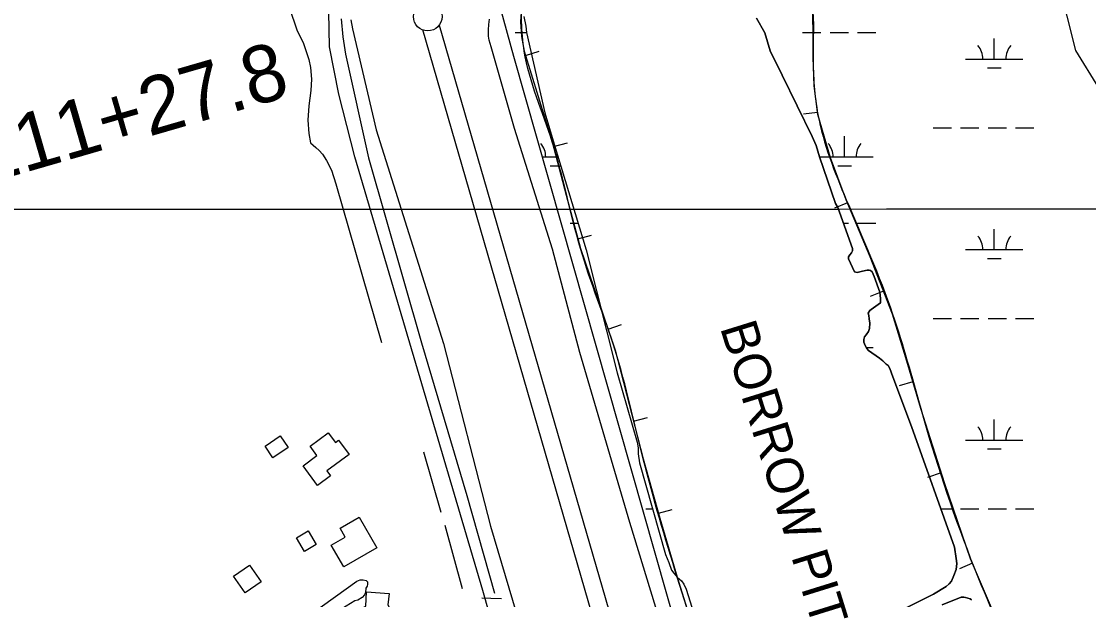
# Model space of a CAD drawing. Extents: x 3281947 to 3319794, y 715894 to 741249.
# Drawn here: x 3291541 to 3293405, y 732714 to 733724 of the extents above; entities that cross this region are included whole.
import ezdxf

# ---------------------------------------------------------------- set-up
doc = ezdxf.new("R2010")
doc.units = 0
for name, color, linetype in [('V-BLDG-OTLN', 7, 'Continuous'), ('V-BORW-IDEN', 7, 'Continuous'), ('V-BORW-LINE', 7, 'Continuous'), ('V-DTCH-CNTR', 7, 'Continuous'), ('V-GRID-MAJR', 7, 'Continuous'), ('V-LEVE-TOET', 7, 'Continuous'), ('V-ROAD-CNTR', 7, 'Continuous'), ('V-SITE-VEGE', 7, 'Continuous'), ('V-SURV-IDEN', 7, 'Continuous'), ('V-SURV-LINE', 7, 'Continuous'), ('V-TOPO-SHOR', 7, 'Continuous'), ('V-WETL-SWMP', 7, 'Continuous')]:
    doc.layers.add(name, color=color, linetype=linetype)

msp = doc.modelspace()

# ---------------------------------------------------------------- linework, layer by layer
at = {"layer": 'V-BLDG-OTLN'}
for points in [[(3291980.4, 732961.6), (3291966.5, 732981.9), (3291993.1, 733000.2), (3292007.1, 732979.9)], [(3292074.6, 732938.7), (3292080.9, 732930.3), (3292058.4, 732913.6), (3292033, 732947.7), (3292057.2, 732965.7), (3292045.2, 732981.9), (3292077, 733005.6), (3292089.7, 732988.6), (3292094.9, 732992.5), (3292113.4, 732967.6)], [(3292130.9, 732858), (3292161.8, 732804.7), (3292103.9, 732771.1), (3292081.9, 732808.9), (3292106.5, 732823.2), (3292097.6, 732838.7)], [(3292035.2, 732798.1), (3292021.3, 732821.8), (3292042.1, 732834), (3292056, 732810.3)], [(3291931.6, 732725.8), (3291911.5, 732755.2), (3291939.6, 732774.5), (3291959.8, 732745)], [(3292142.5, 732702.7), (3292143.7, 732727.6), (3292183.2, 732724.9), (3292181.2, 732705.2), (3292200.2, 732667.4), (3292166.1, 732651.6), (3292157.7, 732668.7), (3292127.1, 732655.4), (3292110.3, 732687.3)]]:
    msp.add_lwpolyline(points, close=True, dxfattribs=at)
at = {"layer": 'V-BORW-LINE'}
for p, q in [((3292421.4, 733664.4), (3292445.4, 733671.7)), ((3292931.5, 733564.9), (3292906.7, 733561.8)), ((3292470.3, 733505.2), (3292494.6, 733511.4)), ((3292983.8, 733407), (3292960.7, 733397.4)), ((3292512.8, 733344.1), (3292536.9, 733350.5)), ((3293046.7, 733252.7), (3293023.4, 733243.6)), ((3292565.6, 733186.1), (3292589.3, 733194.2)), ((3293097.8, 733094.3), (3293073.8, 733087.3)), ((3292610, 733025.6), (3292634.2, 733031.9)), ((3293147.4, 732935.3), (3293123.6, 732927.6)), ((3292653.6, 732864.8), (3292677.6, 732871.6)), ((3293202, 732777.9), (3293179, 732768.1))]:
    msp.add_line(p, q, dxfattribs=at)
for points in [[(3292416, 733774.3), (3292412.7, 733722.9), (3292414.5, 733697.2), (3292419.2, 733671.8), (3292443.4, 733592.3), (3292468.2, 733513.4), (3292492.4, 733420.2), (3292517.3, 733327.2), (3292547.9, 733238.5), (3292578, 733149.6), (3292602.5, 733054.8), (3292626.9, 732959.9), (3292655.9, 732856.5), (3292686.3, 732753.5), (3292718.4, 732650.6)], [(3293236.9, 732695.8), (3293198.7, 732785.6), (3293153.6, 732916.1), (3293111.5, 733047.6), (3293087.3, 733130.2), (3293062.5, 733212.5), (3293023.2, 733312.7), (3292981.6, 733412.2), (3292953.9, 733485.6), (3292932, 733561), (3292925.7, 733610.9), (3292923.7, 733661.1), (3292923.9, 733706.9), (3292922.7, 733752.5)]]:
    msp.add_lwpolyline(points, dxfattribs=at)
msp.add_spline([(3293535.9, 730584.4), (3293535.4, 730585.3), (3293497, 730657.8), (3293473.2, 730709), (3293458.5, 730751), (3293474.3, 730774.9), (3293498.1, 730803.8), (3293503.4, 730822.7), (3293477.8, 730865.6), (3293442, 730902.7), (3293433.9, 730945), (3293411.4, 730975.9), (3293373.6, 730999.6), (3293329.4, 731009.5), (3293303.1, 731048.1), (3293262.2, 731107.9), (3293205.3, 731214.8), (3293152.6, 731305), (3293107.1, 731394.1), (3293067.5, 731500.7), (3293026.1, 731639), (3292993.6, 731735.4), (3292952.7, 731872.8), (3292925.4, 731981.1), (3292877.6, 732144.9), (3292823.1, 732324.3), (3292751.1, 732547.8), (3292686.3, 732753.5), (3292626.9, 732959.9), (3292578, 733149.6), (3292517.3, 733327.2), (3292468.2, 733513.4), (3292419.2, 733671.8), (3292416, 733774.3), (3292443.1, 733955.9), (3292470.5, 734116.1), (3292505.3, 734342.4), (3292539, 734502.7), (3292585.4, 734750.4), (3292605.6, 734909.3), (3292653.5, 735109.1), (3292667, 735197.9), (3292695.9, 735272.4), (3292816.4, 735423.9), (3292992.8, 735589.4), (3293118.5, 735717.8), (3293151.4, 735720.6), (3293212.8, 735688.5), (3293267.6, 735628.9), (3293299.6, 735578.7), (3293301.8, 735551.8), (3293258, 735404.8), (3293178.9, 735247.8), (3293118.6, 735154.6), (3293020.3, 735075.8), (3292963, 735023.3), (3292899.5, 734947.4), (3292877.5, 734825.5), (3292893.6, 734715.3), (3292909.1, 734596.9), (3292894.2, 734486.7), (3292877, 734359.2), (3292869.2, 734210.8), (3292882, 734024.1), (3292899.4, 733885.4), (3292922.7, 733752.5), (3292923.7, 733661.1), (3292932, 733561), (3292981.6, 733412.2), (3293062.5, 733212.5), (3293111.5, 733047.6), (3293198.7, 732785.6), (3293276, 732606.5), (3293315.6, 732497), (3293336.7, 732448.1), (3293389.1, 732447.8), (3293396.1, 732434.3), (3293380.9, 732420.2), (3293299, 732384.1), (3293266.7, 732364.9), (3293242, 732348.4), (3293249.1, 732332.4), (3293352.9, 732375.1), (3293457.9, 732401.3), (3293485.1, 732328.5), (3293556.5, 732096.9), (3293588.1, 731935.2), (3293608.4, 731793.7), (3293628.6, 731696.8), (3293641.6, 731601.6), (3293698.6, 731490.3), (3293768.8, 731439), (3293849.4, 731356), (3293937.4, 731250.3), (3293976, 731184.6), (3294065.4, 731012.3)], degree=3, dxfattribs=at)
at = {"layer": 'V-DTCH-CNTR'}
msp.add_lwpolyline([(3292009.4, 733746.9), (3292022.3, 733708.8), (3292033.9, 733685), (3292042.9, 733657.3), (3292045.8, 733643), (3292047.8, 733623), (3292046.3, 733603.2), (3292043.3, 733576.1), (3292041.5, 733551.3), (3292043.2, 733527.7), (3292046.1, 733511.8), (3292055.4, 733503.3), (3292061.2, 733498.5), (3292066.6, 733491.9), (3292074, 733481.1), (3292082.6, 733464.2), (3292090.1, 733440.1), (3292169.7, 733163.1)], dxfattribs=at)
at = {"layer": 'V-GRID-MAJR'}
msp.add_spline([(3286081.5, 733394.4), (3291329.7, 733395.6), (3296577.9, 733397.5), (3301826.1, 733400.1), (3307074.3, 733403.6), (3312322.5, 733407.8), (3317570.7, 733412.7)], degree=3, dxfattribs=at)
at = {"layer": 'V-LEVE-TOET'}
for points in [[(3292116.6, 733726.4), (3292119.1, 733710.8), (3292160.5, 733534.6), (3292278.1, 733161.5), (3292360.2, 732842.1), (3292398.4, 732713.4), (3292457.8, 732512.4), (3292537.4, 732193.7), (3292611.6, 731908.2), (3292708.8, 731568.3), (3292740.3, 731460.7), (3292780.4, 731364), (3292812.9, 731289.4), (3292841.9, 731225.5), (3292874.9, 731155.3), (3293007.9, 730907.9)], [(3292728.7, 732439.8), (3292603.7, 732848.8), (3292516.4, 733145.5), (3292468.8, 733326.1), (3292402.3, 733536.6), (3292361.3, 733679.4), (3292358, 733691), (3292357, 733697.8), (3292356.8, 733702.6), (3292356.7, 733709.2), (3292357.2, 733718), (3292358.6, 733727.4)]]:
    msp.add_lwpolyline(points, dxfattribs=at)
at = {"layer": 'V-ROAD-CNTR'}
for points in [[(3292971.1, 730923), (3292872, 731117), (3292817.2, 731219.5), (3292783.6, 731284), (3292753.8, 731349.2), (3292730.2, 731404.5), (3292711.3, 731460.3), (3292655.9, 731658.9), (3292493.2, 732214.9), (3292347.1, 732730.2), (3292123.3, 733487.2), (3292095.5, 733596.9), (3292079.2, 733679.3), (3292077.9, 733740.5)], [(3292379.2, 732715.4), (3292360.7, 732715.9), (3292345, 732716.4)]]:
    msp.add_lwpolyline(points, dxfattribs=at)
at = {"layer": 'V-SITE-VEGE'}
for points in [[(3292824.7, 733729.2), (3292839.3, 733704), (3292848.4, 733672.5), (3292869.6, 733630), (3292922, 733522.9), (3292929.1, 733507.1), (3292935, 733487.2), (3292962.5, 733405.8), (3292967, 733398.8), (3292992.6, 733327.1), (3292992.6, 733323.1), (3292990.7, 733319.4), (3292987.5, 733316.1), (3292985.2, 733312.6), (3292985.4, 733309.1), (3292995.8, 733286.7), (3293000.5, 733285.5), (3293005.4, 733286.3), (3293010.1, 733287.5), (3293018.2, 733289.1), (3293021.7, 733289.6), (3293024.1, 733288.7), (3293026.7, 733286.4), (3293030.2, 733278.2), (3293039.9, 733250.9), (3293041.4, 733240.1), (3293041.4, 733232.2), (3293028.8, 733223.7), (3293024.9, 733220.9), (3293022.5, 733219), (3293020, 733214.3), (3293020.9, 733209.9), (3293021.4, 733204.5), (3293022.9, 733196.6), (3293022.2, 733187.7), (3293020.1, 733182.5), (3293016.2, 733176.2), (3293013.6, 733172.9), (3293012.2, 733168), (3293012.3, 733163.8), (3293014.6, 733157.7), (3293017.5, 733152.6), (3293020.3, 733149.3), (3293039.8, 733135.4), (3293045.4, 733131), (3293051.3, 733125.4), (3293054.8, 733122.6), (3293057.6, 733117.7), (3293062.6, 733103.2), (3293095.2, 733016.2), (3293170.6, 732805.9), (3293173.5, 732786), (3293174.7, 732776.9), (3293173.5, 732766.9), (3293169.6, 732756.3), (3293165.2, 732746.5), (3293161.3, 732741.5), (3293155.9, 732737.3), (3293133.8, 732723.7), (3293058, 732685.9)], [(3293148.8, 732704.8), (3293182.2, 732718.5), (3293186.9, 732718.3), (3293189.9, 732717.8), (3293193.9, 732716.5), (3293197.6, 732715.5), (3293200.4, 732713.9)]]:
    msp.add_lwpolyline(points, dxfattribs=at)
msp.add_lwpolyline([(3292032.1, 732673.3), (3292048.2, 732689.7), (3292127.1, 732746.5), (3292132.5, 732748.5), (3292137.9, 732748.4), (3292143, 732747.7), (3292145.3, 732744.9), (3292145.6, 732741.2), (3292144.6, 732737.6), (3292142.5, 732733.9), (3292141.8, 732726.8), (3292140.4, 732722.7), (3292136.2, 732718), (3292128.4, 732713.4), (3292123.4, 732712.2), (3292070.1, 732679.3), (3292049.3, 732659.7), (3292045.7, 732654.9), (3292040, 732652.2), (3292034.3, 732653.4), (3292031.6, 732656.7), (3292030.4, 732661.1), (3292030.7, 732665.1)], close=True, dxfattribs=at)
at = {"layer": 'V-SURV-LINE'}
for points in [[(3292688.7, 732167.4), (3292241.9, 733708.8)], [(3292270.7, 733717.1), (3292717.5, 732175.8)]]:
    msp.add_lwpolyline(points, dxfattribs=at)
msp.add_circle((3292250.7, 733732.1), 25, dxfattribs=at)
at = {"layer": 'V-TOPO-SHOR'}
for p, q in [((3292274, 732866), (3292244, 732971.5)), ((3292311.3, 732732.7), (3292281.3, 732843.5))]:
    msp.add_line(p, q, dxfattribs=at)
msp.add_lwpolyline([(3292099.2, 733728.4), (3292102.3, 733696.8), (3292106.8, 733666.2), (3292147.3, 733485.4), (3292239.5, 733162.4), (3292319, 732896), (3292367, 732725.1)], dxfattribs=at)
at = {"layer": 'V-WETL-SWMP'}
for p, q in [((3292403.3, 733704.3), (3292423.4, 733704.3)), ((3292905.2, 733704.3), (3292937.2, 733704.3)), ((3292953.2, 733704.3), (3292985.2, 733704.3)), ((3293001.2, 733704.3), (3293033.2, 733704.3)), ((3293240, 733657.9), (3293240, 733693.9)), ((3293190, 733657.9), (3293290, 733657.9)), ((3293228, 733642.4), (3293252, 733642.4)), ((3293133.2, 733537.8), (3293165.2, 733537.8)), ((3293181.2, 733537.8), (3293213.2, 733537.8)), ((3293229.2, 733537.8), (3293261.2, 733537.8)), ((3293277.2, 733537.8), (3293309.2, 733537.8)), ((3292978.6, 733487.1), (3292978.6, 733523.1)), ((3292450.4, 733487.1), (3292478.3, 733487.1)), ((3292476.7, 733487.1), (3292476.7, 733492.5)), ((3292935.1, 733487.1), (3293028.6, 733487.1)), ((3292464.7, 733471.6), (3292483, 733471.6)), ((3292966.6, 733471.6), (3292990.6, 733471.6)), ((3292483.2, 733371.6), (3292483.3, 733371.6)), ((3292499.3, 733371.6), (3292513.4, 733371.6)), ((3292976.7, 733371.6), (3292985.2, 733371.6)), ((3293001.2, 733371.6), (3293033.2, 733371.6)), ((3293240, 733325.2), (3293240, 733361.2)), ((3293190, 733325.2), (3293290, 733325.2)), ((3293228, 733309.8), (3293252, 733309.8)), ((3293133.2, 733205.1), (3293165.2, 733205.1)), ((3293181.2, 733205.1), (3293213.2, 733205.1)), ((3293229.2, 733205.1), (3293261.2, 733205.1)), ((3293277.2, 733205.1), (3293309.2, 733205.1)), ((3293016.5, 733154.4), (3293028.6, 733154.4)), ((3293240, 732992.5), (3293240, 733028.5)), ((3293190, 732992.5), (3293290, 732992.5)), ((3293228, 732977.1), (3293252, 732977.1)), ((3292631.3, 732872.5), (3292643.3, 732872.5)), ((3293146.7, 732872.5), (3293165.2, 732872.5)), ((3293181.2, 732872.5), (3293213.2, 732872.5)), ((3293229.2, 732872.5), (3293261.2, 732872.5)), ((3293277.2, 732872.5), (3293309.2, 732872.5))]:
    msp.add_line(p, q, dxfattribs=at)
for points in [[(3293242.1, 736812), (3293232.1, 735969.6), (3293242.1, 735829.2), (3293272.1, 735779.1), (3293346.9, 735732.1), (3293357.8, 735673.5), (3293299.3, 735657.1), (3293212, 735769), (3293184.2, 735772.3), (3293151.3, 735776), (3293101.8, 735759), (3293021.6, 735688.8), (3292891.3, 735548.4), (3292761.1, 735398), (3292660.9, 735297.7), (3292620.8, 735237.5), (3292370.3, 733773.3), (3292400.3, 733663), (3292811.2, 732218.9), (3292828.6, 732036.6), (3293081.7, 731326.4), (3293270.4, 730981.3)], [(3294819.9, 730595.5), (3294614.9, 731005.5), (3294474.6, 731296.3), (3294354.4, 731617.2), (3294214.1, 731787.7), (3294073.8, 731978.2), (3293562.7, 733201.7), (3293462.5, 733542.7), (3293382.4, 733673.1), (3293352.3, 733793.4), (3293412.4, 733883.7), (3293492.6, 733913.7), (3293612.8, 733883.7), (3293673, 733813.5), (3293763.1, 733713.2)], [(3292418.6, 733732.2), (3292421.7, 733715.4), (3292423.4, 733704.2), (3292455.2, 733564.3), (3292471.6, 733509.4), (3292527.6, 733325), (3292581.4, 733109.9), (3292616.3, 732989.2), (3292618.2, 732978.9), (3292618.3, 732968.4), (3292620.7, 732953), (3292665.6, 732793), (3292671.8, 732779), (3292676.5, 732765.5), (3292680.5, 732760.1), (3292686.2, 732753.6), (3292690.4, 732750.1), (3292693.7, 732746.9), (3292698.1, 732741.3), (3292701.9, 732732.2), (3292732.3, 732636.5)], [(3293051.3, 733125.4), (3293045.4, 733131), (3293039.8, 733135.4), (3293020.3, 733149.3), (3293017.5, 733152.6), (3293014.6, 733157.7), (3293012.3, 733163.8), (3293012.2, 733168), (3293013.6, 733172.9), (3293016.2, 733176.2), (3293020.1, 733182.5), (3293022.2, 733187.7), (3293022.9, 733196.6), (3293021.4, 733204.5), (3293020.9, 733209.9), (3293020, 733214.3), (3293022.5, 733219), (3293024.9, 733220.9), (3293028.8, 733223.7), (3293041.4, 733232.2), (3293041.4, 733240.1), (3293039.9, 733250.9), (3293030.2, 733278.2), (3293026.7, 733286.4), (3293024.1, 733288.7), (3293021.7, 733289.6), (3293018.2, 733289.1), (3293010.1, 733287.4), (3293005.4, 733286.3), (3293000.5, 733285.5), (3292995.8, 733286.7), (3292985.4, 733309.1), (3292985.2, 733312.6), (3292987.5, 733316.1), (3292990.7, 733319.4), (3292992.6, 733323.1), (3292992.6, 733327.1), (3292967, 733398.8), (3292962.5, 733405.8), (3292935, 733487.2), (3292929.1, 733507.1), (3292922, 733522.9), (3292869.6, 733630), (3292848.4, 733672.5), (3292839.3, 733704), (3292824.7, 733729.2)], [(3293058, 732685.9), (3293133.8, 732723.7), (3293155.9, 732737.3), (3293161.3, 732741.5), (3293165.2, 732746.5), (3293169.6, 732756.3), (3293173.5, 732766.9), (3293174.7, 732776.9), (3293173.5, 732786), (3293170.6, 732805.9), (3293095.2, 733016.2), (3293062.6, 733103.2), (3293057.6, 733117.7), (3293054.8, 733122.6), (3293051.3, 733125.4)], [(3293200.4, 732713.9), (3293197.6, 732715.5), (3293193.9, 732716.5), (3293189.9, 732717.8), (3293186.9, 732718.3), (3293182.2, 732718.5), (3293148.8, 732704.8)]]:
    msp.add_lwpolyline(points, dxfattribs=at)
for centre, start, end in [((3293184.8, 733658.4), 359.2282, 40.7718), ((3293295.3, 733658.4), 139.2282, 180.7718), ((3292421.4, 733487.5), 359.2282, 40.7718), ((3292923.3, 733487.5), 359.2282, 40.7718), ((3293033.8, 733487.5), 139.2282, 180.7718), ((3293184.8, 733325.7), 359.2282, 40.7718), ((3293295.3, 733325.7), 139.2282, 180.7718), ((3293184.8, 732993), 359.2282, 40.7718), ((3293295.3, 732993), 139.2282, 180.7718)]:
    msp.add_arc(centre, 35.2, start, end, dxfattribs=at)

# ---------------------------------------------------------------- texts
at = {"layer": 'V-BORW-IDEN'}
msp.add_text('BORROW PIT', height=64, rotation=287.2718, dxfattribs=at).set_placement((3292760.7, 733189.2))
at = {"layer": 'V-SURV-IDEN'}
msp.add_text('3211+27.8', height=100, rotation=16.1508, dxfattribs=at).set_placement((3291402.9, 733417.8))

doc.saveas('drawing.dxf')
